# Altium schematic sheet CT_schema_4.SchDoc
size 406 x 321 mm
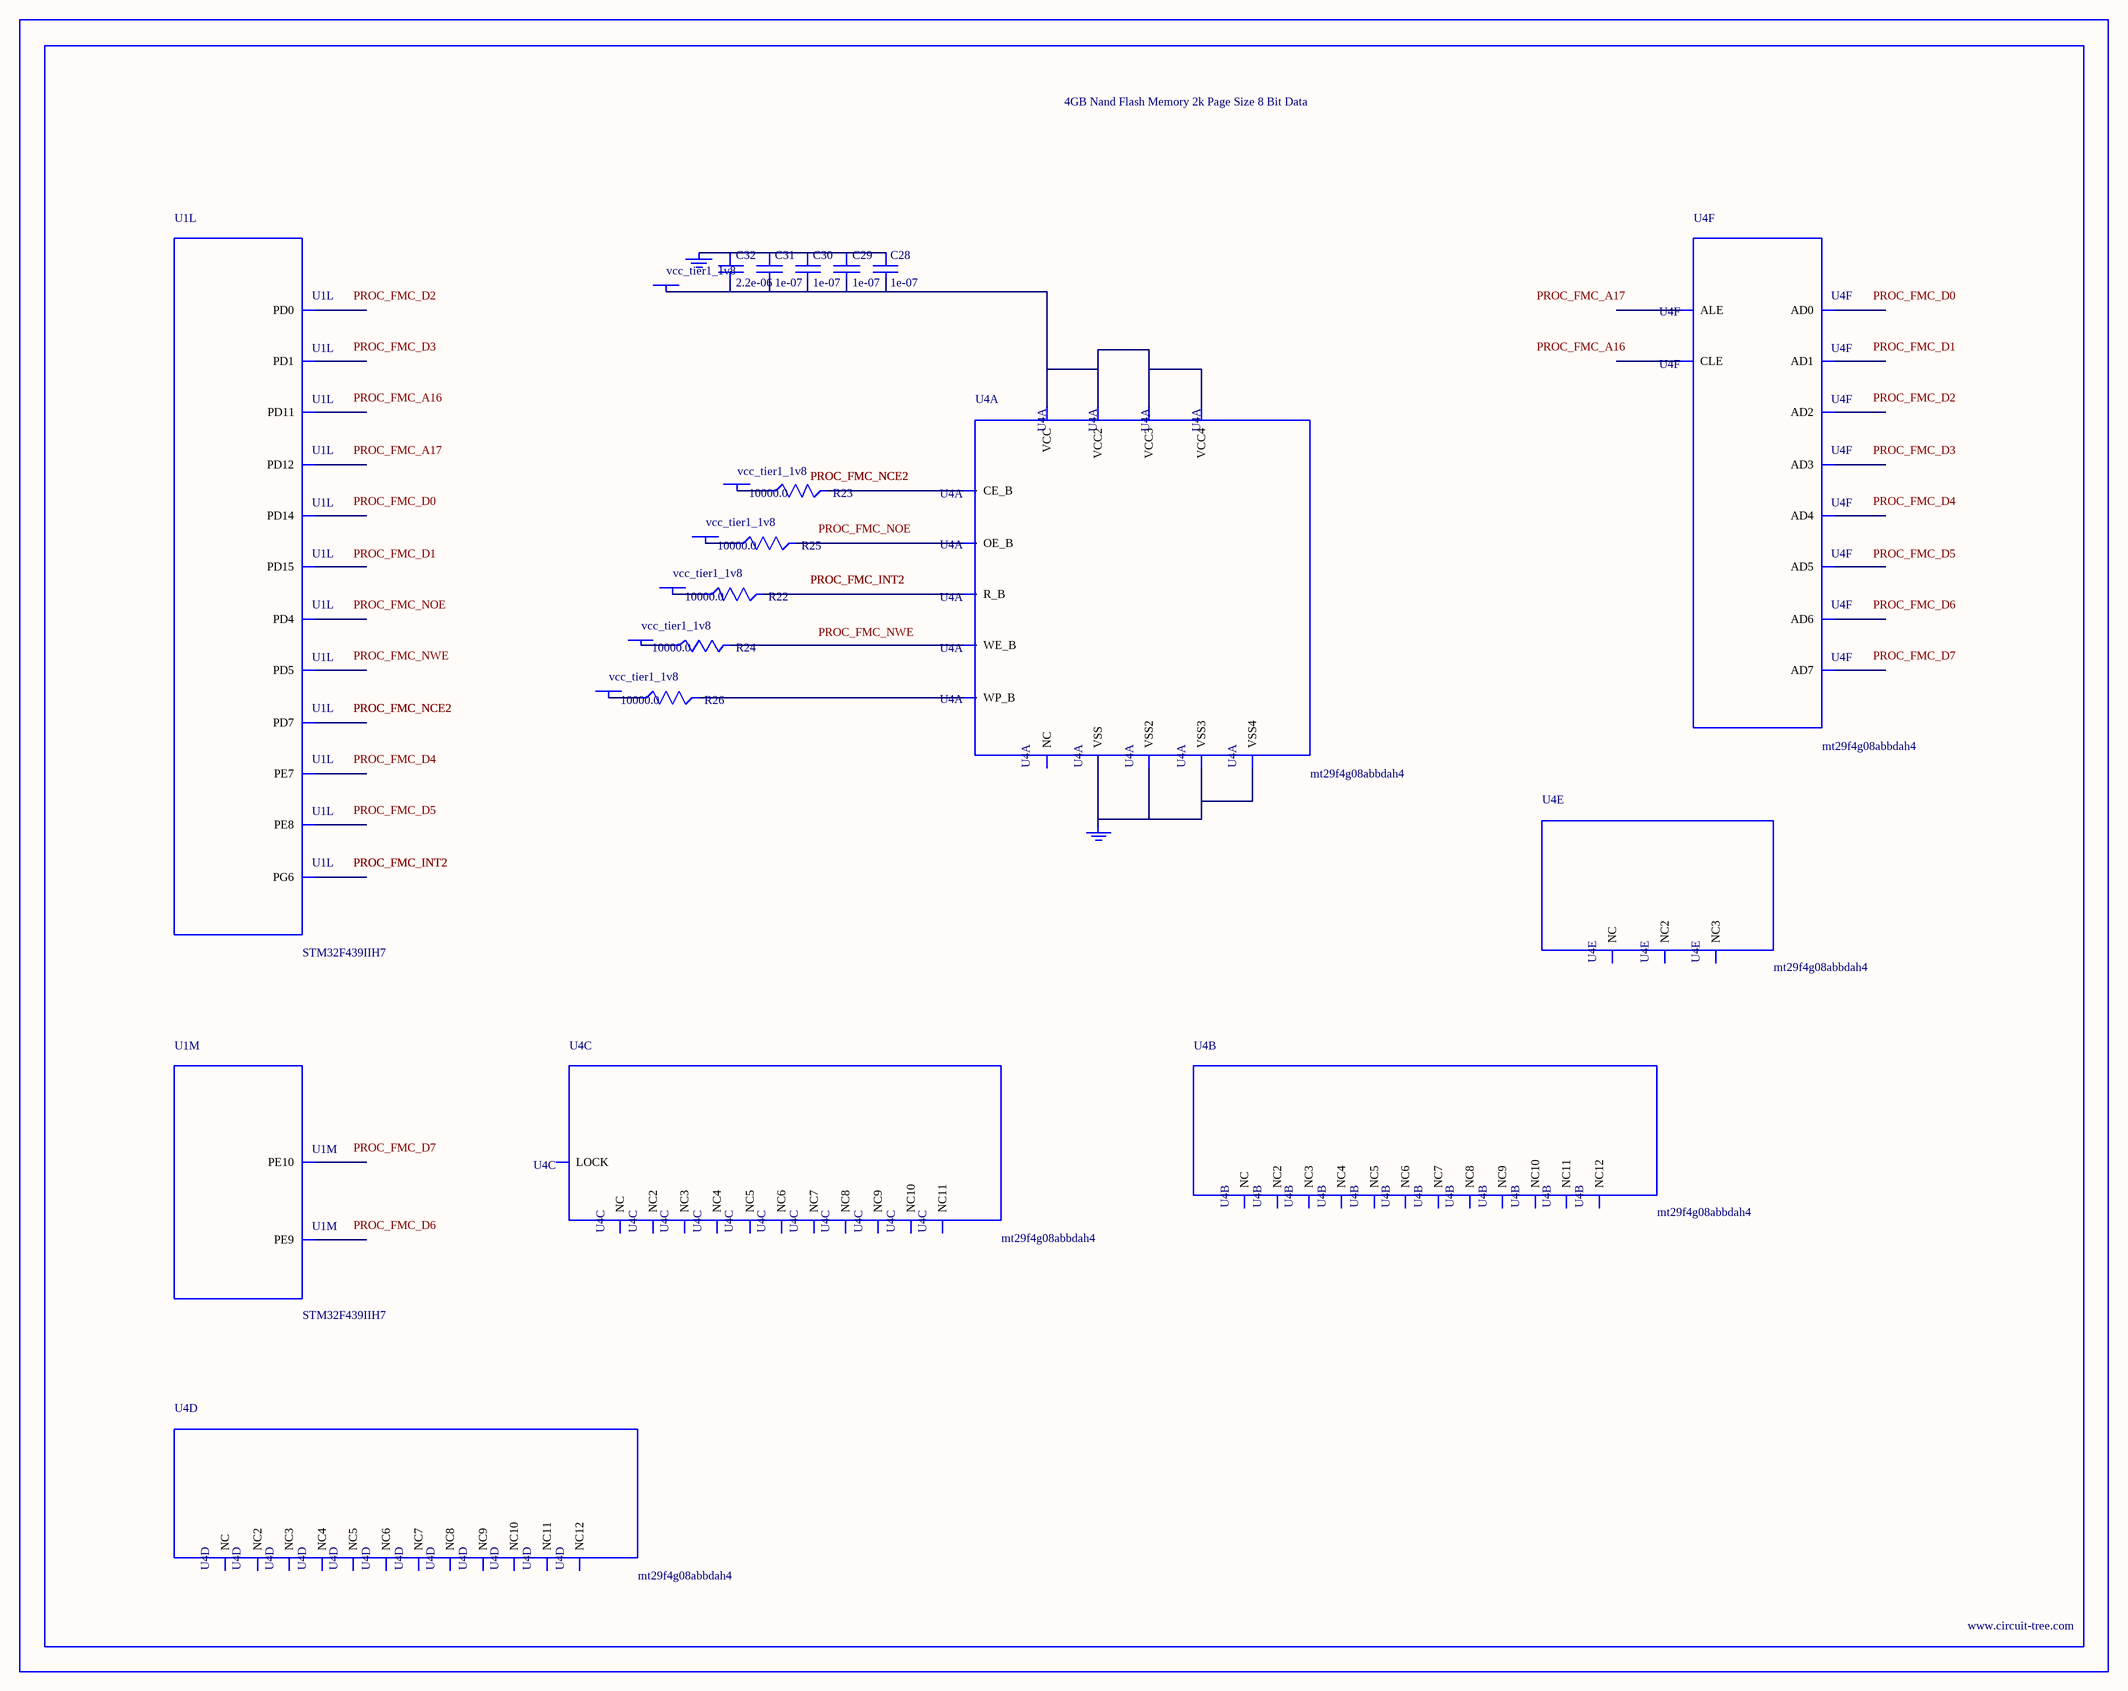
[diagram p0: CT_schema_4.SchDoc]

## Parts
BORDER3  (no value)
C28  1e-07  [C0402]
C29  1e-07  [C0402]
C30  1e-07  [C0402]
C31  1e-07  [C0402]
C32  2.2e-06  [C0603]
GND_INSTANCE_3_0  (no value)
GND_INSTANCE_3_1  (no value)
POWER_INSTANCE_3_0  vcc_tier1_1v8
POWER_INSTANCE_3_1  vcc_tier1_1v8
POWER_INSTANCE_3_2  vcc_tier1_1v8
POWER_INSTANCE_3_3  vcc_tier1_1v8
POWER_INSTANCE_3_4  vcc_tier1_1v8
POWER_INSTANCE_3_5  vcc_tier1_1v8
R22  10000.0  [R0603]
R23  10000.0  [R0603]
R24  10000.0  [R0603]
R25  10000.0  [R0603]
R26  10000.0  [R0603]
U1  STM32F439IIH7  [UFBGA176_25]  (parts L,M of 14)
U4  mt29f4g08abbdah4  [VFBGA-63]  (parts A,B,C,D,E,F of 6)

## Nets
NetC28_1: C28.1 C29.1 C30.1 C31.1 C32.1 GND_INSTANCE_3_0.0(GND)
NetC28_2: C28.2 C29.2 C30.2 C31.2 C32.2 POWER_INSTANCE_3_0.0(PWR) U4.D3(VCC) U4.G4(VCC2) U4.H8(VCC3) U4.J6(VCC4)
NetGND_INSTANCE_3_1_0: GND_INSTANCE_3_1.0(GND) U4.C5(VSS) U4.F7(VSS2) U4.K3(VSS3) U4.K8(VSS4)
NetPOWER_INSTANCE_3_1_0: POWER_INSTANCE_3_1.0(PWR) R22.1
NetPOWER_INSTANCE_3_2_0: POWER_INSTANCE_3_2.0(PWR) R23.1
NetPOWER_INSTANCE_3_3_0: POWER_INSTANCE_3_3.0(PWR) R24.1
NetPOWER_INSTANCE_3_4_0: POWER_INSTANCE_3_4.0(PWR) R25.1
NetPOWER_INSTANCE_3_5_0: POWER_INSTANCE_3_5.0(PWR) R26.1
NetR22_2: R22.2 U4.C8(R_B)
NetR23_2: R23.2 U4.C6(CE_B)
NetR24_2: R24.2 U4.C7(WE_B)
NetR25_2: R25.2 U4.D4(OE_B)
NetR26_2: R26.2 U4.C3(WP_B)

Not connected (* = marked no-connect by the designer): U1 A11(PD7) B12(PD0) C11(PD5) C12(PD1) D10(PD4) J15(PG6) L14(PD15) M14(PD14) N13(PD12) N14(PD11) P8(PE8) P9(PE9) R8(PE7) R9(PE10); U4 A1(NC) A2(NC3) A9(NC4) A10(NC2) B1(NC5) B9(NC7) B10(NC6) C4(ALE) D5(CLE) D6(NC8) D7(NC9) D8(NC10) E3(NC11) E4(NC12) E5(NC) E6(NC2) E7(NC3) E8(NC4) F3(NC5) F4(NC6) F5(NC7) F6(NC8) F8(NC9) G3(NC) G5(LOCK) G6(NC10) G7(NC11) G8(NC) H3(NC2) H4(AD0) H5(NC3) H6(NC4) H7(NC5) J3(NC6) J4(AD1) J5(NC7) J7(AD5) J8(AD7) K4(AD2) K5(AD3) K6(AD4) K7(AD6) L1(NC8) L2(NC10) L9(NC11) L10(NC9) M1(NC12) M2(NC2) M9(NC3) M10(NC)

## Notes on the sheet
- Labels drawn without touching a wire or pin: PROC_FMC_A16, PROC_FMC_A17, PROC_FMC_D0, PROC_FMC_D1, PROC_FMC_D2, PROC_FMC_D3, PROC_FMC_D4, PROC_FMC_D5, PROC_FMC_D6, PROC_FMC_D7, PROC_FMC_NOE, PROC_FMC_NWE

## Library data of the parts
BORDER3 = BORDER_PAGE3
C28-C31 = C0402C104K3RACTU
C32 = C0603C225K8RACTU
GND_INSTANCE_3_0 GND_INSTANCE_3_1 = GND
POWER_INSTANCE_3_0-POWER_INSTANCE_3_5 = PWR
R22-R26 = RC0603JR-0710KL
